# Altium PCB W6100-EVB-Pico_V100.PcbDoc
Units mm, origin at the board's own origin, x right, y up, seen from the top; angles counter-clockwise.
Board outline 75 x 21 mm, 2 copper layers (Top Layer, Bottom Layer); 85 components, 83 nets, 391 pads, 152 vias.
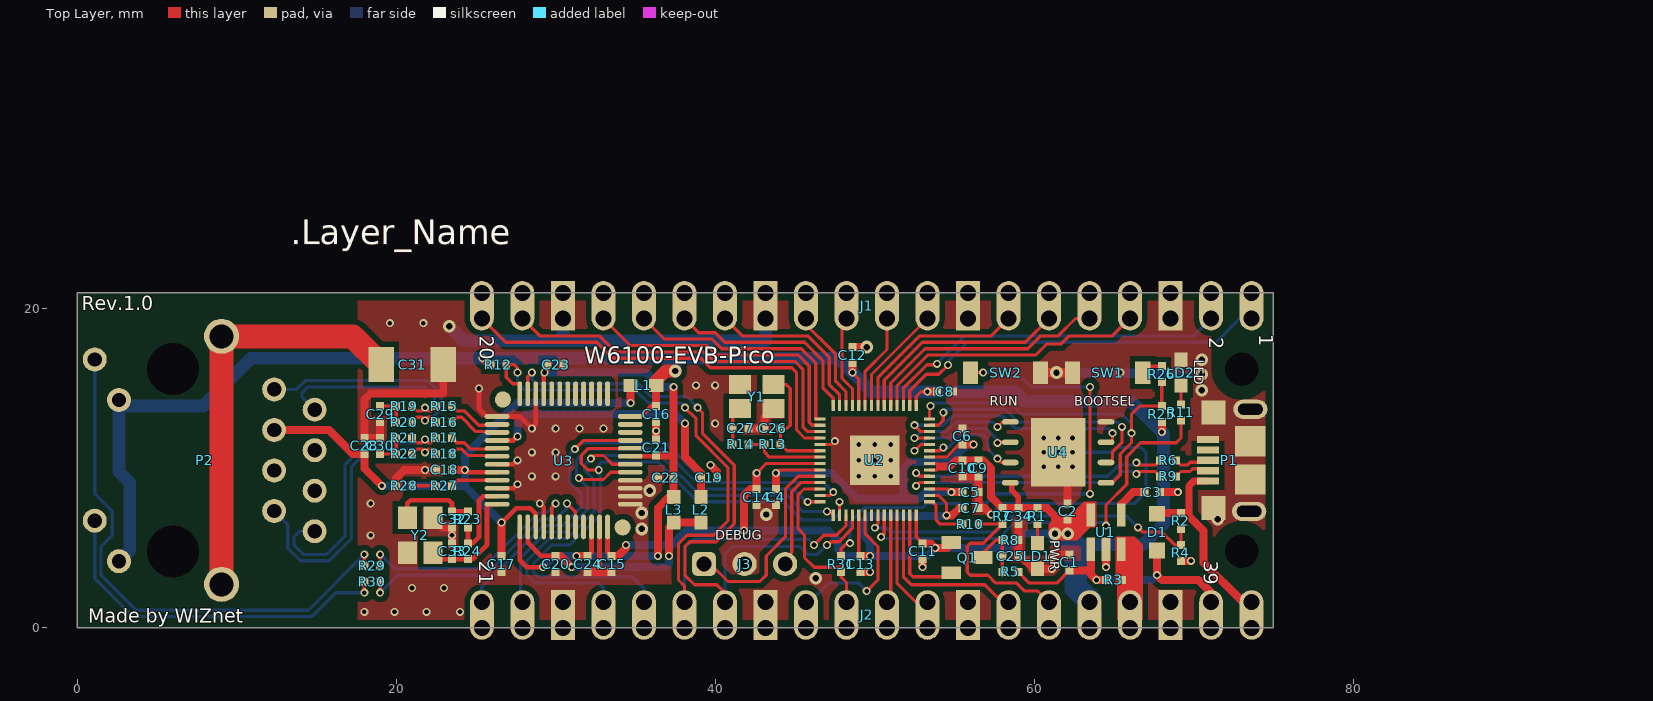
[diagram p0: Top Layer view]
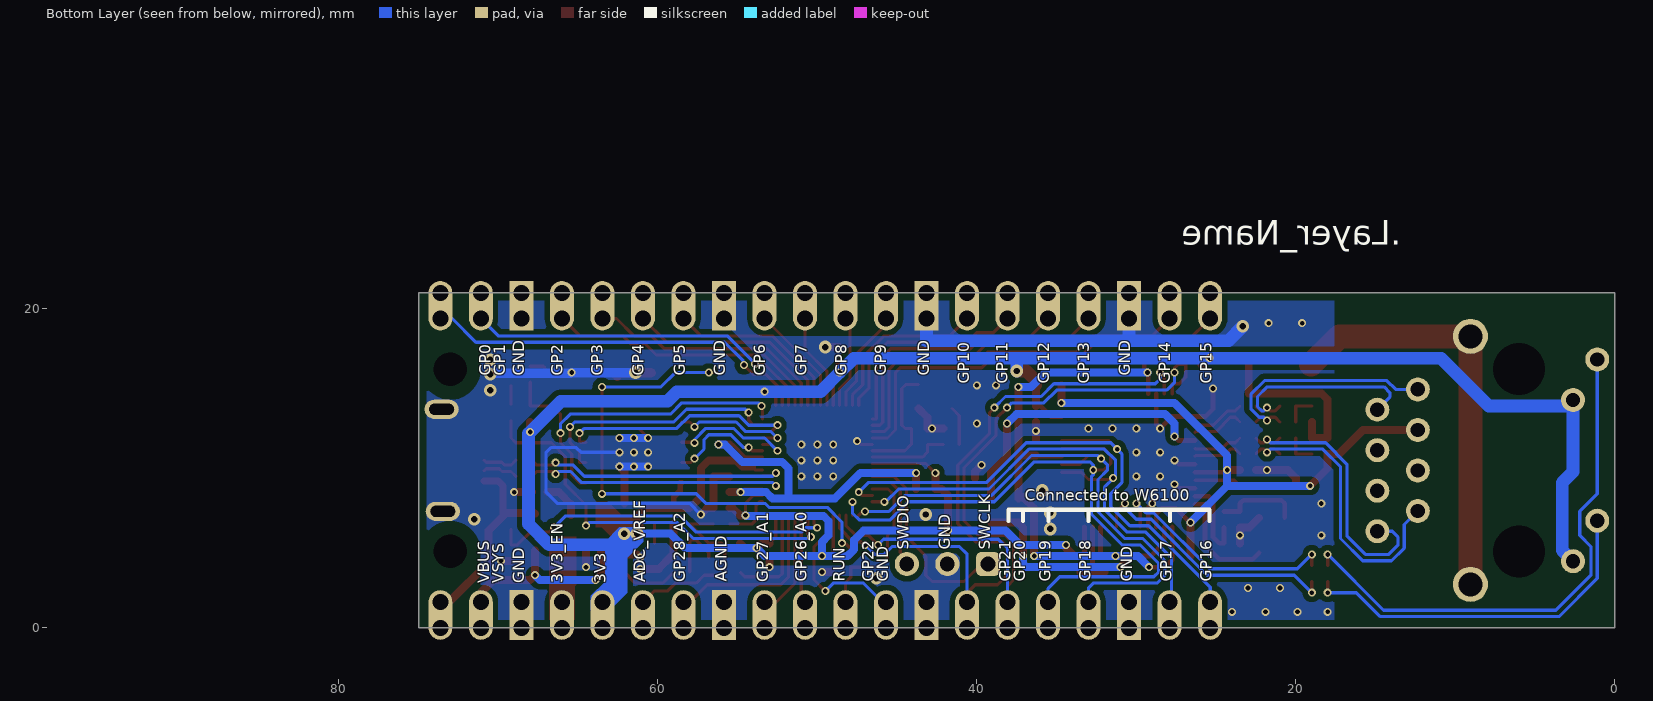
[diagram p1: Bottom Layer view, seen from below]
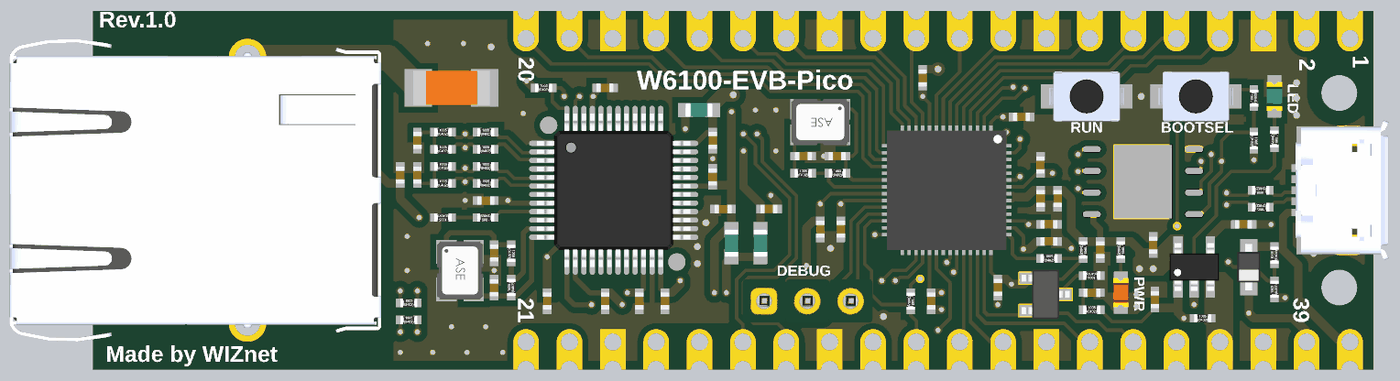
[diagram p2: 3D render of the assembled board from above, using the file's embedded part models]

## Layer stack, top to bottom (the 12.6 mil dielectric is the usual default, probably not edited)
Top Solder: solder mask 0.0102, Solder Resist, Dk 3.5
Top Layer: signal copper 0.0356
Dielectric1: prepreg 0.32, FR-4, Dk 4.8
Bottom Layer: signal copper 0.0356
Bottom Solder: solder mask 0.0102, Solder Resist, Dk 3.5

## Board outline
0,0 75,0 75,21 0,21

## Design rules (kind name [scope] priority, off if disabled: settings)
BoardOutlineClearance [All] p1: gap=0.5 ignorepadtopadclearanceinfootprint=FALSE
Clearance [All] p1: gap=0.2 ignorepadtopadclearanceinfootprint=FALSE except(0: Arc-Hole Track-Hole SMDPad-Hole THPad-Hole Via-Hole Fill-Hole Poly-Hole Region-Hole Text-Hole; 0.35: Arc-Poly Track-Poly SMDPad-Poly THPad-Poly Via-Poly Fill-Poly Poly-Poly Poly-Region Poly-Text)
DiffPairsRouting [All] p1: maxlimit=0.2 minlimit=0.2 mostfreqgap=0.2 toplayer_minwidth=0.2 toplayer_maxwidth=0.2 toplayer_prefwidth=0.2 bottomlayer_minwidth=0.2 bottomlayer_maxwidth=0.2 bottomlayer_prefwidth=0.2 maxuncoupledlength=15.24
HoleSize [All] p1: absolutevalues=TRUE maxlimit=4.064 minlimit=0.025 maxpercent=80.000 minpercent=20.000
PlaneClearance [All] p1: clearance=0.3
PlaneConnect [All] p1: planeconnectstyle=Direct reliefexpansion=0.508 reliefentries=4 reliefconductorwidth=0.254 reliefairgap=0.254
PolygonConnect [All] p1: connectstyle=Direct reliefconductorwidth=0.6 reliefentries=4 polygonreliefangle="45 Angle" airgapwidth=0.35
RoutingVias [All] p1: holewidth=0.3 width=0.5 viastyle="Through Hole" minholewidth=0.3 minwidth=0.5 maxholewidth=0.5 maxwidth=0.8
SolderMaskExpansion [All] p1: expansion=0 istentingtop=FALSE
Width [All] p1: maxlimit=2 minlimit=0.1 preferedwidth=0.2 minimp=50.000000 maximp=50.000000 favimp=50.000000
26 further rules are at their usual default settings.

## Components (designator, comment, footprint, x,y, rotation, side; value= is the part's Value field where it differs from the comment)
C1 "1uF" CAP-0402 62.2,4.1 r270 top
C2 "1uF" CAP-0402 62.1,7.3 r270 top
C3 "0.1uF" CAP-0402 67.4,8.5 r180 top
C4 "1uF" CAP-0402 43.8,8.2 r90 top
C5 "0.1uF" CAP-0402 56,8.5 r180 top
C6 "0.1uF" CAP-0402 55.5,12 r270 top
C7 "1uF" CAP-0402 56,7.5 r180 top
C8 "0.1uF" CAP-0402 54.4,14.8 r180 top
C9 "0.1uF" CAP-0402 56.5,10 r90 top
C10 "0.1uF" CAP-0402 55.5,10 r90 top
C11 "0.1uF" CAP-0402 53,4.8 r90 top
C12 "0.1uF" CAP-0402 48.6,17.1 r270 top
C13 "0.1uF" CAP-0402 49.1,4 r90 top
C14 "0.1uF" CAP-0402 42.6,8.2 r90 top
C15 "0.1uF" CAP-0402 33.5,4 r90 top
C16 "0.1uF" CAP-0402 36.3,13.4 r90 top
C17 "0.1uF" CAP-0402 26.6,4 r90 top
C18 "0.1uF" CAP-0402 23,9.9 r0 top
C19 "0.1uF" CAP-0402 39.6,9.4 r180 top
C20 "1uF" CAP-0402 30,4 r90 top
C21 "0.1uF" CAP-0402 36.3,11.3 r270 top
C22 "0.1uF" CAP-0402 36.9,9.4 r0 top
C23 "0.1uF" CAP-0402 30,16.5 r180 top
C24 "0.1uF" CAP-0402 32,4 r90 top
C25 "0.1uF" CAP-0402 58.5,4.5 r0 top
C26 "15pF" CAP-0402 43.6,12.5 r180 top
C27 "15pF" CAP-0402 41.6,12.5 r0 top
C28 "0.1uF" CAP-0402 18,11.4 r270 top
C29 "0.1uF" CAP-0402 19,13.4 r90 top
C30 "0.1uF" CAP-0402 19,11.4 r270 top
C31 "1nF/2kV" CAP-1808 21,16.5 r180 top
C32 "18pF" CAP-0402 23.5,6.8 r90 top
C33 "18pF" CAP-0402 23.5,4.8 r270 top
C34 "0.1uF" CAP-0402 59,7 r90 top
D1 "BAT60A" SOD-323(1-C,2-A) 67.7,6 r90 top
J1 "2.54mm 1x20 Pin Header DIP" IDC-1X20 73.63,19.39 r180 top
J2 "2.54mm 1x20 Pin Header DIP" IDC-1X20 25.37,1.61 r0 top
J3 "2.54mm 1x3 Pin Header DIP" IDC-1X3 39.3,4 r0 top
L1 "HH-1M1608-121JT" IND-0603 35.5,15.2 r180 top
L2 "HH-1M1608-121JT" IND-0603 39.1,7.4 r270 top
L3 "HH-1M1608-121JT" IND-0603 37.4,7.4 r90 top
LD1 "Red" LED-0603-RED 60.2,4.5 r270 top
LD2 "Green" LED-0603-GREEN 69.2,16 r90 top
P1 "Micro USB" "Micro 5P B DBX 6.4" 75,10.5 r180 top
P2 "RB1-125BAG1A" RB1-125BAG1A 6,10.5 r270 top
Q1 "Q-2N7002" SOT23-3L 55.8,4.4 r270 top
R1 "470R" RES-0402 60.2,7 r270 top
R2 "5.6K" RES-0402 69.2,6.7 r90 top
R3 "100K" RES-0402 65,3 r0 top
R4 "10K" RES-0402 69.2,4.7 r90 top
R5 "200K" RES-0402 58.5,3.5 r0 top
R6 "27R" RES-0402 68.4,10.5 r180 top
R7 "200R" RES-0402 58,7 r270 top
R8 "100K" RES-0402 58.5,5.5 r180 top
R9 "27R" RES-0402 68.4,9.5 r180 top
R10 "1R" RES-0402 56,6.5 r0 top
R11 "470R" RES-0402 69.2,13.5 r270 top
R12 "4.7K" RES-0402 26.4,16.5 r0 top
R13 "NC" RES-0402 43.6,11.5 r0 top
R14 "1K" RES-0402 41.6,11.5 r0 top
R15 "3.3R" RES-0402 23,13.9 r0 top
R16 "3.3R" RES-0402 23,12.9 r0 top
R17 "3.3R" RES-0402 23,11.9 r0 top
R18 "3.3R" RES-0402 23,10.9 r0 top
R19 "49.9R" RES-0402 20.5,13.9 r0 top
R20 "49.9R" RES-0402 20.5,12.9 r0 top
R21 "49.9R" RES-0402 20.5,11.9 r0 top
R22 "49.9R" RES-0402 20.5,10.9 r0 top
R23 "0R" RES-0402 24.5,6.8 r270 top
R24 "1M" RES-0402 24.5,4.8 r90 top
R25 "NC" RES-0402 68,13.4 r270 top
R26 "1K" RES-0402 68,15.9 r90 top
R27 "12K/1%" RES-0402 23,8.9 r180 top
R28 "300R" RES-0402 20.5,8.9 r180 top
R29 "470R" RES-0402 18.5,3.9 r0 top
R30 "470R" RES-0402 18.5,2.9 r0 top
R31 "1K" RES-0402 47.9,4 r270 top
SW1 "PTS820" 1185A 64.6,16 r180 top
SW2 "PTS820" 1185A 58.2,16 r0 top
U1 "LM8805SF5-33V" SOT-23-5L 64.5,6 r90 top
U2 "RP2040" QFN56(0.4/7X7) 50,10.5 r270 top
U3 "W5100S" LQFP48(0.5/9.0) 30.5,10.5 r0 top
U4 "W25Q16JVZPIM" WSON8(6X5_1.27) 61.5,11 r180 top
Y1 "12MHz" OSC-TZ1067B 42.6,14.5 r180 top
Y2 "25MHz" OSC-82J0626 21.5,5.8 r270 top

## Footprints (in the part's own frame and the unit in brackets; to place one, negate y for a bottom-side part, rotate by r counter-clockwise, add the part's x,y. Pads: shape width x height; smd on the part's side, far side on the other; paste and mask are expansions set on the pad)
1185A [mm]
  rect 0.95x1.4 smd: 1(-2.2,0) 2(2.2,0)
  body extent -2.18,-1.45 2.18,1.45, height 1.7
CAP-0402 [mm]
  rect 0.5x0.5 smd: 1(-0.5,0) 2(0.5,0)
  body extent -0.48,-0.25 0.52,0.25, height 0.6
CAP-1808 [mm] "Ceramic CAP 1808(4520)"
  rect 1.6x2.2 smd: 1(-1.95,0) 2(1.95,0)
  body extent -2.25,-1.02 2.25,1.01, height 2
IDC-1X3 [mil]
  rrect50% 60x60 hole 36: 1(0,0)
  round 60 hole 36: 2(100,0) 3(200,0)
  body extent -49,-49 251,51, height 336
IDC-1X20 [mm]
  oval 1.5x2.5 hole 1 copper offset 0,-0.5: 1(0,0) 2(2.54,0) 4(7.62,0) 5(10.16,0) 6(12.7,0) 7(15.24,0) 9(20.32,0) 10(22.86,0) 11(25.4,0) 12(27.94,0) 14(33.02,0) 15(35.56,0) 16(38.1,0) 17(40.64,0) 19(45.72,0) 20(48.26,0)
  oval 1.5x2.5 hole 1 copper offset 0,0.5: 1(0,-1.61) 2(2.54,-1.61) 4(7.62,-1.61) 5(10.16,-1.61) 6(12.7,-1.61) 7(15.24,-1.61) 9(20.32,-1.61) 10(22.86,-1.61) 11(25.4,-1.61) 12(27.94,-1.61) 14(33.02,-1.61) 15(35.56,-1.61) 16(38.1,-1.61) 17(40.64,-1.61) 19(45.72,-1.61) 20(48.26,-1.61)
  rect 1.5x2.5 hole 1 copper offset 0,0.5: 3(5.08,-1.61) 8(17.78,-1.61) 13(30.48,-1.61) 18(43.18,-1.61)
  rect 1.5x2.5 hole 1 copper offset 0,-0.5: 3(5.08,0) 8(17.78,0) 13(30.48,0) 18(43.18,0)
IND-0603 [mm] "Inductor 0603(1608)"
  rect 0.89x0.82 smd: 1(-0.8,0) 2(0.8,0)
  body extent -0.8,-0.4 0.8,0.4, height 0.95
LED-0603-GREEN [mm] "LED-0603-GREEN"
  rect 0.89x0.82 smd: 1(-0.8,0) 2(0.8,0)
  body extent -0.85,-0.45 0.85,0.45, height 0.9
LED-0603-RED [mm] "LED-0603-RED"
  rect 0.89x0.82 smd: 1(-0.8,0) 2(0.8,0)
  body extent -0.85,-0.45 0.85,0.45, height 0.9
LQFP48(0.5/9.0) [mm]
  round 1.016 smd: 0(-3.81,3.81) 0(3.7,-4.2)
  oval 1.55x0.3 smd: 1(-4.175,2.75) 2(-4.175,2.25) 3(-4.175,1.75) 4(-4.175,1.25) 5(-4.175,0.75) 6(-4.175,0.25) 7(-4.175,-0.25) 8(-4.175,-0.75) 9(-4.175,-1.25) 10(-4.175,-1.75) 11(-4.175,-2.25) 12(-4.175,-2.75) 25(4.175,-2.75) 26(4.175,-2.25) 27(4.175,-1.75) 28(4.175,-1.25) 29(4.175,-0.75) 30(4.175,-0.25) 31(4.175,0.25) 32(4.175,0.75) 33(4.175,1.25) 34(4.175,1.75) 35(4.175,2.25) 36(4.175,2.75)
  oval 0.3x1.55 smd: 13(-2.75,-4.175) 14(-2.25,-4.175) 15(-1.75,-4.175) 16(-1.25,-4.175) 17(-0.75,-4.175) 18(-0.25,-4.175) 19(0.25,-4.175) 20(0.75,-4.175) 21(1.25,-4.175) 22(1.75,-4.175) 23(2.25,-4.175) 24(2.75,-4.175) 37(2.75,4.175) 38(2.25,4.175) 39(1.75,4.175) 40(1.25,4.175) 41(0.75,4.175) 42(0.25,4.175) 43(-0.25,4.175) 44(-0.75,4.175) 45(-1.25,4.175) 46(-1.75,4.175) 47(-2.25,4.175) 48(-2.75,4.175)
  body extent -4.5,-4.5 4.5,4.5, height 1.5
"Micro 5P B DBX 6.4" [mm]
  rect 1.38x0.45 smd: 1(4.11,1.3) 2(4.11,0.65) 3(4.11,0) 4(4.11,-0.65) 5(4.11,-1.3)
  oval 2.15x1.2 hole 0.7 slot 1.55 at 0 deg: 6(1.524,3.2) 7(1.45,-3.2)
  rect 1.9x1.9 smd: 8(1.45,1.2) 9(1.45,-1.2)
  rect 1.5x1.5 smd: 10(3.75,-3) 11(3.75,3)
  body extent -0.88,-4.1 4.55,4.1, height 2.68
OSC-82J0626 [mm]
  rect 1.4x1.2 smd: 1(-1.1,-0.8) 2(1.1,-0.8) 3(1.1,0.8) 4(-1.1,0.8)
  body extent -1.7,-1.35 1.7,1.35, height 1.06
OSC-TZ1067B [mm]
  rect 1.4x1.2 smd: 1(-1.05,-0.75) 2(1.05,-0.75) 3(1.05,0.75) 4(-1.05,0.75)
  body extent -1.7,-1.35 1.7,1.35, height 1.06
QFN56(0.4/7X7) [mm]
  rect 0.7x0.2 smd: 1(-3.44,2.6) 2(-3.44,2.2) 3(-3.44,1.8) 4(-3.44,1.4) 5(-3.44,1) 6(-3.44,0.6) 7(-3.44,0.2) 8(-3.44,-0.2) 9(-3.44,-0.6) 10(-3.44,-1) 11(-3.44,-1.4) 12(-3.44,-1.8) 13(-3.44,-2.2) 14(-3.44,-2.6) 29(3.44,-2.6) 30(3.44,-2.2) 31(3.44,-1.8) 32(3.44,-1.4) 33(3.44,-1) 34(3.44,-0.6) 35(3.44,-0.2) 36(3.44,0.2) 37(3.44,0.6) 38(3.44,1) 39(3.44,1.4) 40(3.44,1.8) 41(3.44,2.2) 42(3.44,2.6)
  rect 0.2x0.7 smd: 15(-2.6,-3.44) 16(-2.2,-3.44) 17(-1.8,-3.44) 18(-1.4,-3.44) 19(-1,-3.44) 20(-0.6,-3.44) 21(-0.2,-3.44) 22(0.2,-3.44) 23(0.6,-3.44) 24(1,-3.44) 25(1.4,-3.44) 26(1.8,-3.44) 27(2.2,-3.44) 28(2.6,-3.44) 43(2.6,3.44) 44(2.2,3.44) 45(1.8,3.44) 46(1.4,3.44) 47(1,3.44) 48(0.6,3.44) 49(0.2,3.44) 50(-0.2,3.44) 51(-0.6,3.44) 52(-1,3.44) 53(-1.4,3.44) 54(-1.8,3.44) 55(-2.2,3.44) 56(-2.6,3.44)
  rect 3.1x3.1 smd: 57(0,0)
  body extent -3.5,-3.5 3.5,3.5, height 0.8
RB1-125BAG1A [mm]
  round 1.5 hole 0.9: L1(6.325,-3.38) L2(3.785,-4.9) L3(-3.785,-3.38) L4(-6.325,-4.9) R1(-4.445,6.35) R2(-3.175,8.89) R3(-1.905,6.35) R4(-0.635,8.89) R5(0.635,6.35) R6(1.905,8.89) R7(3.175,6.35) R8(4.445,8.89)
  round 2.2 hole 1.5: S1(-7.775,3.05) S2(7.775,3.05)
  round 3 hole 3.25 unplated paste+0 mask+0.102: ""(-5.715,0) ""(5.715,0)
  body extent -8.87,-10.89 8.88,10.89, height 14.02
RES-0402 [mm]
  rect 0.5x0.5 smd: 1(-0.5,0) 2(0.5,0)
  body extent -0.5,-0.25 0.5,0.25, height 0.35
SOD-323(1-C,2-A) [mm]
  rect 1x1 smd: 1(-1.15,0) 2(1.15,0)
  body extent -1.35,-0.67 1.35,0.68, height 0.79
SOT23-3L [mm]
  rect 0.8x1.2 smd paste-0.07: 1(-0.95,-1) 2(0.95,-1) 3(0,1)
  body extent -1.45,-1.4 1.45,1.4, height 1.28
SOT-23-5L [mm]
  rect 1.45x0.55 smd: 1(-1.075,0.95) 2(-1.075,0) 3(-1.075,-0.95) 4(1.075,-0.95) 5(1.075,0.95)
  body extent -1.4,-1.45 1.4,1.45, height 1.45
WSON8(6X5_1.27) [mm]
  oval 1.05x0.35 smd mask+0.05: 1(-3,1.905) 2(-3,0.635) 3(-3,-0.635) 4(-3,-1.905) 5(3,-1.905) 6(3,-0.635) 7(3,0.635) 8(3,1.905)
  rect 3.4x4.3 smd mask+0.05: 9(0,0)
  body extent -3,-2.5 3,2.5, height 0.8

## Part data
C1 C2 C3 C4 C5 C6 C7 C8 C9 C10 C11 C12 C13 C14 C15 C16 C17 C18 C19 C20 C21 C22 C23 C24 C25 C26 C27 C28 C29 C30 C32 C33 C34: library part CAP-0402, "Ceramic CAP 0402(1005)"
C31: library part CAP-1808, "Ceramic CAP 1808(4520)"
D1: library part DIODE-BAT60A, "Silicon Schottky Diode"
L1 L2 L3: library part IND-0603, "Inductor 0603(1608)"
LD1 LD2: library part LED-0603, "LED-0603"
P1: library part "Micro USB 5P DBX6.4", "Micro USB B Connector SMD"
Q1: "N-Channel 60-V (D-S) MOSFET"
R1 R2 R3 R4 R5 R6 R7 R8 R9 R10 R11 R12 R13 R14 R15 R16 R17 R18 R19 R20 R21 R22 R23 R24 R25 R26 R27 R28 R29 R30 R31: library part RES-0402, "RES-0402"
SW1 SW2: library part ITS-1107(SMD), "TACT Switch (SMD)"
U1: "600mA CMOS LDO Regulator"
U2: "Raspverry Pi, Dual ARM Cortex-M0+ @ 133MHz"
U3: "WIZnet Hardwired TCP/IP Chip"
U4: "3V 16M-BIT / SERIAL FLASH MEMORY WITH / DUAL/QUAD SPI, QPI & DTR"
Y1: library part OSC-TZ1067B-12MHz, "X-tal 12MHz,3.2x2.5 SMD, CL=20pF"
Y2: library part OSC-82J0626-25MHz, "X-tal 25MHz,3.2x2.5 SMD, CL=18pF"

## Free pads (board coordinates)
  round 0 hole 2.1 unplated: 0(73,4.8) 0(73,16.2)
  round 0 on Mech16 paste+0 mask+0: 1(96.4,35.9)

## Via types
v1: diameter 0.5, hole 0.3, Top Layer to Bottom Layer, tented both sides, 133 vias
v2: diameter 0.8, hole 0.4, Top Layer to Bottom Layer, tented both sides, 15 vias
v3: diameter 0.5, hole 0.3, Top Layer to Bottom Layer, 4 vias

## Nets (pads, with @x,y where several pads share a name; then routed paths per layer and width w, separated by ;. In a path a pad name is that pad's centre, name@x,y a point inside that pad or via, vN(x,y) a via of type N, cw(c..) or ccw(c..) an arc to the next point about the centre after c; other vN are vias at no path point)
1V1: C4.2 C5.2 C6.2 U2.23 U2.45 U2.50 | length 27.8
  Top Layer w0.2: v1(43.8,9.7) 44,9.9 U2.23 ; U2.45 54.6,8.7 v1(54.8,8.5) ; U2.50 54.5,10.7 55.3,11.5 C6.2
  Top Layer w0.5: C4.2 v1(43.8,9.7) ; v1(54.8,8.5) C5.2 ; C6.2 v1(56.2,11.5)
  Bottom Layer w0.5: v1(43.8,9.7) 47.3,9.7 48.9,8.1 51.8,8.1 ; v1(54.8,8.5) 53.2,8.5 52.8,8.1 51.8,8.1 ; v1(56.2,11.5) 55.8,11.5 54.7,10.4 52.2,10.4 51.8,10 51.8,8.1
1V2A: C19.2 L2.1 U3.4 | length 18.2
  Top Layer w0.3: U3.4 27.35,11.75 v1(27.6,12)
  Top Layer w0.5: v1(38.1,12.8) 38.1,10.7 39.1,9.7 C19.2 L2.1
  Bottom Layer w0.5: v1(27.6,12) 27.6,12.8 28.2,13.4 37.5,13.4 v1(38.1,12.8)
1V2D: C21.2 C22.2 C23.2 C24.2 L3.2 U3.13 U3.22 U3.31 U3.45 | length 38.3
  Top Layer w0.3: U3.13 27.75,4.25 28.2,3.8 v1(29.2,3.8) ; U3.45 29.25,15.9 29.25,16 v1(29.3,16) 29.5,16.2 C23.2 ; C24.2 32.25,4.75 U3.22 ; U3.31 36.25,10.75 C21.2
  Top Layer w0.5: v1(31.3,4.5) C24.2 ; C21.2 37.4,10.8 ; v1(36.4,4.5) 36.4,7.5 37.1,8.2 L3.2 ; L3.2@37.4,8.1 C22.2 37.4,10.8 ; v1(37.4,15.1) 37.4,10.8
  Bottom Layer w0.5: v1(29.2,3.8) 29.9,4.5 v1(31.3,4.5) ; v1(29.3,16) 35.7,16 36.6,15.1 v1(37.4,15.1) ; v1(31.3,4.5) v1(36.4,4.5)
1V2O: C20.2 L2.2 L3.1 U3.14 | length 15
  Top Layer w0.3: U3.14 28.25,5.35 29.1,4.5 C20.2
  Top Layer w0.5: C20.2 30.3,4.5 v1(31,3.8) ; v1(37.1,4.5) 37.1,6.3 L3.1 L2.2
  Bottom Layer w0.5: v1(31,3.8) 36.9,3.8 37.1,4 v1(37.1,4.5)
3V3: C2.2 C7.2 C8.2 C9.2 C10.2 C11.2 C12.2 C13.2 C14.2 C15.2 C16.2 C34.2 J2.16 L1.1 P2.L1 P2.L3 Q1.1 R1.1 R7.1 R12.1 R25.2 U1.5 U2.1 U2.10 U2.22 U2.33 U2.42 U2.44 U2.48 U2.49 U3.24 U3.36 U4.8 | length 176.9
  Top Layer w0.2: v1(42.6,9.7) 43.2,10.3 U2.22 ; v1(48.6,16) 49,15.6 U2.10 ; U2.33 49,4.6 C13.2 ; U2.42 52.6,5.7 C11.2 ; U2.1 52.6,14.5 52.9,14.8 v1(53.3,14.8) ; U2.44 54,8.3 54.5,7.8 v1(54.5,7.05) ; U2.48 53.9,9.9 54.1,10.1 53.9,10.3 U2.49 ; Q1.1 Q1.1@54.85,5.3
  Top Layer w0.3: U3.24 33.25,4.75 C15.2 ; U3.36 35.35,13.25 36,13.9 C16.2
  Top Layer w0.35: U4.8 58.6,9.095 58.6,8.6 59,8.2 C34.2
  Top Layer w0.5: v1(25.4,16.9) 25.8,16.5 R12.1 ; C15.2 33.9,4.5 34.4,5 v1(34.4,5.2) ; C16.2 L1.1 ; v1(41.8,6.1) 41.8,8.3 42.2,8.7 C14.2 v1(42.6,9.7) ; v1(48.6,16) C12.2 ; C13.2 v1(49.7,4.5) ; C11.2 53.5,5.3 v1(53.8,5) 54.55,5 Q1.1@54.85,5.3 ; v1(53.3,14.8) C8.2 ; 54.1,10.1 54.7,10.1 55.1,10.5 C10.2 C9.2 56.8,10.5 57.3,10 57.3,8.2 R7.1 C34.2 R1.1 60.8,7.5 61.3,7 v2(61.3,5.9) ; v1(54.5,7.05) 54.85,7.05 55.3,7.5 C7.2 ; v1(68,12.275) R25.2
  Top Layer w0.8: L1.1 36.3,15.5 36.9,16.1 v2(37.5,16.1)
  Bottom Layer w0.5: v1(34.4,5.2) 37.3,5.2 38.2,6.1 47.09,6.1 47.7,5.49 47.7,4.9 48.1,4.5 v1(49.7,4.5) ; v1(54.5,7.05) 54.45,7 49.6,7 49.307,6.707 49.307,5.778 49.7,5.385 v1(49.7,4.5) ; v2(61.3,5.9) 59.2,5.9 58.3,5 v1(53.8,5) 53.3,4.5 v1(49.7,4.5)
  Bottom Layer w0.8: P2.L1 3.3,4.855 3.3,9.1 2.62,9.78 P2.L3 3.005,13.9 7.9,13.9 10.9,16.9 v1(25.4,16.9) 37.5,16.9 ; v2(37.5,16.1) 37.5,16.9 ; v2(62.1,5.9) 62.8,5.2 66.8,5.2 68.1,6.5 68.1,12.175 v1(68,12.275) 66.075,14.2 59.39,14.2 59.095,14.495 58.79,14.8 v1(53.3,14.8) 49.8,14.8 v1(48.6,16) 47.7,16.9 37.5,16.9
3V3_EN: J2.17 R3.2 U1.3
3V3A: C17.2 C18.2 C28.2 L1.2 P2.R3 U3.8 U3.15 | length 40.4
  Top Layer w0.3: v1(24.3,9.9) 24.45,9.75 U3.8 ; v1(26.6,6.6) 26.613,6.6 27.513,7.5 28.407,7.5 28.75,7.157 U3.15
  Top Layer w0.5: P2.R3 15.795,12.405 17.3,10.9 C28.2 18,10 v1(19.1,8.9) ; C18.2 v1(24.3,9.9) ; C17.2 v1(26.6,6.6) ; v1(34.7,14.1) L1.2
  Bottom Layer w0.5: v1(19.1,8.9) 24.3,8.9 ; v1(26.6,6.6) 24.3,8.9 ; v1(34.7,14.1) 27.6,14.1 24.3,10.8 v1(24.3,9.9) 24.3,8.9
ACTn: R30.2 U3.20 | length 16.6
  Top Layer w0.2: v1(19,2.2) R30.2 ; v1(30.7,7.8) 31.25,7.25 U3.20
  Bottom Layer w0.2: v1(19,2.2) 20.1,3.3 25.566,3.3 29.066,6.8 30,6.8 30.7,7.5 v1(30.7,7.8)
ADC_VREF: J2.15 R7.2 R10.2 | length 11.8
  Top Layer w0.2: R10.2 R7.2 56.8,5.3 56,5.3 55.8,5.1 55.8,3.5 56,3.3 57.1,3.3 57.6,2.8 58.9,2.8 59.4,2.3 60.24,2.3 J2.15@60.93,1.61
CHGND: C31.2 P2.S1 P2.S2 | length 26.3
  Top Layer w1.5: P2.S2 P2.S1 17.275,18.275 C31.2
GND: C1.1 C2.1 C3.1 C4.1 C5.1 C6.1 C7.1 C8.1 C9.1 C10.1 C11.1 C12.1 C13.1 C14.1 C15.1 C16.1 C17.1 C18.1 C19.1 C20.1 C21.1 C22.1 C23.1 C24.1 C25.2 C26.2 C27.2 C28.1 C29.1 C30.1 C31.1 C32.1 C33.1 C34.1 J1.3 J1.8 J1.13 J1.18 J2.3 J2.8 J2.13 J2.18 J3.2 LD1.2 LD2.2 P1.5 P1.6 P1.7 P1.8 P1.9 P1.10 P1.11 R4.1 R8.1 R28.2 SW1.2 SW2.2 U1.2 U2.19 U2.57 U3.1 U3.7 U3.10 U3.16 U3.23 U3.25 U3.26 U3.27 U3.28 U3.46 U4.4 U4.9 Y1.2 Y1.4 Y2.2 Y2.4 | length 111.7
  Top Layer w0.2: U2.19 47.3,11.5 v1(47.5,11.7) ; v1(60.6,11.9) U4.9@61.1,12.4
  Top Layer w0.3: v1(25.2,15) 25.2,13.7 25.65,13.25 U3.1 27.75,13.25 v1(28.5,12.5) 28.75,12.75 U3.46 ; U3.10 27.35,8.75 v1(27.6,9) ; U3.7 27.35,10.25 v1(27.6,10.5) ; v1(29,7.8) 29.25,7.55 U3.16 ; 32.75,3.5 U3.23
  Top Layer w0.5: C29.1 C30.1 C28.1 18,14.3 18.4,14.7 22.95,14.7 C31.1 ; R28.2 20,9.4 20.5,9.9 v1(21.8,9.9) C18.1 ; Y2.4 22.9,6.3 C32.1 v1(23.5,5.8) C33.1 ; C24.1 32.75,3.5 C15.1 ; C21.1 v1(36.3,12.35) C16.1 ; v1(39.7,10.2) 40.1,9.8 C19.1 ; C27.2 C26.2 43.1,13.2 Y1.4 ; C12.1 v2(49.5,17.6) ; C13.1 v1(49.7,3.5) ; v1(53,3.8) C11.1 ; C10.1 C9.1 C5.1 C7.1 56.9,7.5 v1(57.3,7.1) ; C34.1 R8.1 C25.2 59.137,4.5 59.937,3.7 LD1.2 v1(61.1,3.7) ; v1(61.1,4.4) 61.3,4.6 C1.1 ; C2.1 62.1,9.8 v1(62.4,10.1) ; v1(64.5,3.8) U1.2 ; C3.1 v1(69,8.5) ; R4.1 v1(69.825,4.2)
  Top Layer w0.6: SW2.2 v2(61.4,16) 62.325,16 SW1.2@62.55,15.775
  Bottom Layer w0.2: v1(57.3,7.1) 58,7.8 66.3,7.8 67,8.5 67,11 66.7,11.3 65.1,11.3 64.8,11 v1(62.4,11)
  Bottom Layer w0.5: v1(60.6,10.1) v1(61.5,10.1) v1(62.4,10.1) ; v1(60.6,11.9) v1(61.5,11.9) v1(62.4,11.9)
  Bottom Layer w0.6: v2(61.4,16) v1(65.4,16) 65.45,15.95 70.45,15.95 v2(70.5,15.9)
  Bottom Layer w0.8: v2(23.322,18.9) 24.222,18 30.45,18 ; J1.18@30.45,19.39 30.45,18 ; J1.13@43.15,19.39 43.15,18 30.45,18
  other v1: 18,1 19.9,1 21.9,1 24,1 21,2.5 23,2.5 18.4,5.8 18.4,7.8 28.5,9.5 30,9.5 49,9.5 50,9.5 51,9.5 49,10.5 50,10.5 51,10.5 28.5,11 30,11 60.6,11 61.5,11 49,11.5 50,11.5 51,11.5 30,12.5 31.5,12.5 33,12.5 42.8,12.5 40,12.8 38.8,15.2 40,15.2 19.6,19.1 21.7,19.1
  other v2: 46.3,3.1 35.4,6.2 71.5,6.8 43.2,7.1 35.4,7.2 35.9,8.6 70.5,14.9 70.5,16.8
GPIO0: J1.1 U2.2 | length 24.3
  Top Layer w0.2: U2.2 52.2,14.852 53.243,15.895 54.023,15.895 v1(54.595,16.467)
  Bottom Layer w0.2: v1(54.595,16.467) 54.652,16.525 54.652,16.737 55.816,17.9 71.4,17.9 72.89,19.39 J1.1@73.63,19.39
GPIO1: J1.2 U2.3 | length 22.2
  Top Layer w0.2: U2.3 51.8,15.017 53.275,16.493 53.843,16.493 v1(53.9,16.55)
  Bottom Layer w0.2: v1(53.9,16.55) 55.65,18.3 70,18.3 J1.2@71.09,19.39
GPIO2: J1.4 U2.4 | length 19.2
  Top Layer w0.2: U2.4 51.4,15.183 53.317,17.1 60.1,17.1 60.8,17.8 61.7,17.8 62.2,18.3 64.9,18.3 66.01,19.41 J1.4@66.01,21
GPIO3: J1.5 U2.5 | length 15.6
  Top Layer w0.2: U2.5 51,15.349 53.151,17.5 59.606,17.5 60.406,18.3 61.5,18.3 62.59,19.39 J1.5@63.47,19.39
GPIO4: J1.6 U2.6 | length 13.5
  Top Layer w0.2: U2.6 50.6,15.514 52.986,17.9 59.44,17.9 J1.6@60.93,19.39
GPIO5: J1.7 U2.7 | length 11.5
  Top Layer w0.2: U2.7 50.2,15.68 52.82,18.3 57.3,18.3 J1.7@58.39,19.39
GPIO6: J1.9 U2.8 | length 7.5
  Top Layer w0.2: U2.8 49.8,15.456 49.8,15.88 52.62,18.7 53.31,19.39 J1.9@53.31,18.81
GPIO7: J1.10 U2.9 | length 6
  Top Layer w0.2: U2.9 49.4,16.08 50.77,17.45 J1.10@50.77,19.39
GPIO8: J1.11 U2.11 | length 5.8
  Top Layer w0.2: J1.11@47.95,19.17 47.95,15.65 48.6,15 U2.11 ; J1.11@48.23,19.39 J1.11@48.45,19.17
GPIO9: J1.12 U2.12 | length 6.8
  Top Layer w0.2: J1.12@45.31,19.39 47.55,17.15 47.55,15.45 48.2,14.8 U2.12 ; J1.12@45.69,19.39 J1.12@45.81,19.39
GPIO10: J1.14 U2.13 | length 12.4
  Top Layer w0.2: J1.14@40.61,21 40.61,19.39 41.7,18.3 45.8,18.3 47.15,16.95 47.15,15.25 47.8,14.6 U2.13
GPIO11: J1.15 U2.14 | length 14.5
  Top Layer w0.2: J1.15@38.07,21 38.07,19.39 38.96,18.5 40,18.5 40.6,17.9 45.6,17.9 46.75,16.75 46.75,15.05 47.4,14.4 U2.14
GPIO12: J1.16 U2.15 | length 15.7
  Top Layer w0.2: J1.16@35.53,19.39 36.82,18.1 39.8,18.1 40.4,17.5 45.4,17.5 46.3,16.6 46.3,13.1 U2.15
GPIO13: J1.17 U2.16 | length 18.4
  Top Layer w0.2: J1.17@32.99,19.39 34.68,17.7 39.5,17.7 40.1,17.1 45.2,17.1 45.9,16.4 45.9,12.886 46.086,12.7 U2.16
GPIO14: J1.19 U2.17 | length 23.7
  Top Layer w0.2: J1.19@27.91,19.39 29,18.3 32.734,18.3 33.734,17.3 39.3,17.3 39.9,16.7 45,16.7 45.5,16.2 45.5,12.6 45.8,12.3 U2.17
GPIO15: J1.20 U2.18 | length 26.4
  Top Layer w0.2: J1.20@25.37,19.39 26.86,17.9 32.569,17.9 33.569,16.9 39.1,16.9 39.7,16.3 44.8,16.3 45.1,16 45.1,12.4 45.6,11.9 U2.18
GPIO16: J2.1 U2.27 U3.33 | length 37.2
  Top Layer w0.2: v1(31.2,11.2) 31.75,11.75 U3.33 ; U2.27 47.2,8.3 v1(47.4,8.5)
  Bottom Layer w0.2: J2.1@25.37,0 25.37,1.61 25.37,2.539 29.231,6.4 30.4,6.4 31.6,7.6 31.6,8.4 30.9,9.1 30.9,10.9 v1(31.2,11.2) 31.6,11.6 36.9,11.6 39.4,9.1 46.8,9.1 v1(47.4,8.5)
GPIO17: J2.2 U2.28 U3.29 | length 33.7
  Top Layer w0.2: v1(31.45,9.4) 31.55,9.3 33,9.3 33.45,9.75 U3.29 ; v1(45.8,7.9) U2.28
  Bottom Layer w0.2: J2.2@27.91,0 27.91,1.61 27.8,1.72 27.8,3.1 27.8,4.403 29.397,6 30.566,6 32,7.434 32,8.8 v1@31.4,9.4 ; v1(31.45,9.4) 31.3,9.55 31.3,10.5 32,11.2 36.734,11.2 39.234,8.7 44.9,8.7 45.7,7.9 v1(45.8,7.9)
GPIO18: J2.4 U2.29 U3.30 | length 37.4
  Top Layer w0.2: v1(32.2,10.6) 32.4,10.8 33,10.8 33.55,10.25 U3.30 ; v1(47,7.3) 47.16,7.3 U2.29
  Bottom Layer w0.2: J2.4@32.99,0 32.99,1.61 32.99,2.51 32.7,2.8 28.7,2.8 28.2,3.3 28.2,4.2 29.6,5.6 30.731,5.6 32.4,7.269 32.4,9.3 31.8,9.9 31.8,10.2 v1(32.2,10.6) 32.4,10.8 36.569,10.8 39.069,8.3 44.5,8.3 45.5,7.3 v1(47,7.3)
GPIO19: J2.5 U2.30 U3.32 | length 40.8
  Top Layer w0.2: v1(32.7,9.9) 32,9.9 31.6,10.3 31.6,10.8 32.05,11.25 U3.32 ; U2.30 v1(47.8,7.9)
  Bottom Layer w0.2: J2.5@35.53,1.61 35.53,2.47 34.8,3.2 28.9,3.2 28.6,3.5 28.6,4.034 29.766,5.2 30.897,5.2 32.8,7.103 32.8,9.5 32.7,9.6 v1(32.7,9.9) 32.7,10.2 32.9,10.4 36.403,10.4 38.903,7.9 44.3,7.9 45.45,6.75 46.372,6.75 47.35,6.75 47.8,7.2 v1(47.8,7.9)
GPIO20: J2.6 R12.2 U2.31 U3.48 | length 49.3
  Top Layer w0.2: v1(27.6,16) 27.6,16.3 27.4,16.5 R12.2 26.9,15.7 27.3,15.3 27.75,15.3 U3.48 ; J2.6@38.07,0 38.07,1.61 38.07,2.63 37.7,3 37.7,5.266 38.234,5.8 39.9,5.8 40.8,6.7 40.8,10.034 38.8,12.034 38.8,13.1 v1(38.1,13.8) ; v1(46.2,5.2) 46.8,5.8 47.6,5.8 48.2,6.4 U2.31
  Bottom Layer w0.2: v1(27.6,16) 27.6,15.4 28.1,14.9 35,14.9 35.8,14.1 37.8,14.1 v1(38.1,13.8) ; J2.6@38.07,0 38.07,1.61 38.07,4.97 38.65,5.55 45.85,5.55 v1(46.2,5.2)
GPIO21: J2.7 U2.32 U3.47 | length 46.4
  Top Layer w0.2: U3.47 28.25,15.75 v1(28.5,16) ; v1(38.9,13.8) 39.2,13.5 39.2,12.2 41.2,10.2 41.2,6.534 40.066,5.4 38.4,5.4 38.1,5.1 38.1,3.3 38.7,2.7 40.1,2.7 40.61,2.19 40.61,1.61 J2.7@40.61,0 ; v1(47,5.2) 47.067,5.2 47.267,5.4 47.766,5.4 48.6,6.234 U2.32
  Bottom Layer w0.2: v1(28.5,16) 28.5,15.6 28.8,15.3 35.166,15.3 35.966,14.5 38.2,14.5 v1(38.9,13.8) ; J2.7@40.61,0 40.61,1.61 40.61,4.61 41.1,5.1 45.3,5.1 45.8,4.6 46.4,4.6 v1(47,5.2)
GPIO22: J2.9 U2.34 | length 12
  Top Layer w0.2: U2.34 49.4,5.9 50.2,5.1 50.2,3 v1(49.5,2.3)
  Bottom Layer w0.2: J2.9@45.69,0 J2.9@45.69,1.61 ; J2.9@45.69,2.09 J2.9@45.69,1.61 ; v1(49.5,2.3) 49,2.8 47.1,2.8 45.91,1.61 J2.9@45.69,1.61
GPIO24: R2.1 R4.2 U2.36 | length 22.3
  Top Layer w0.2: v1(50.007,6.273) 50.007,6.293 50,6.3 50.2,6.5 U2.36 ; v1(66.5,6.3) 66.8,6 68,6 68.8,5.2 R4.2 R2.1
  Bottom Layer w0.2: v1(50.007,6.273) 50.727,6.273 51,6 57.6,6 58.6,7 65.8,7 v1(66.5,6.3)
GPIO25: R11.2 U2.37 | length 25.9
  Top Layer w0.2: v1(50.409,5.7) 50.4,5.7 50.6,5.9 U2.37 ; v1(64.5,6.4) 64.5,7.7 65.8,9 65.8,10.734 66.666,11.6 68.9,11.6 69.2,11.9 R11.2
  Bottom Layer w0.2: v1(50.409,5.7) 50.509,5.6 57.766,5.6 58.766,6.6 64.3,6.6 v1(64.5,6.4)
GPIO26/ADC0: J2.11 U2.38 | length 7.2
  Top Layer w0.2: J2.11@50.77,0 50.77,1.61 51,1.84 U2.38
GPIO27/ADC1: J2.12 U2.39 | length 6.7
  Top Layer w0.2: U2.39 51.4,2.8 52.59,1.61 J2.12@53.31,1.61
GPIO28/ADC2: J2.14 U2.40 | length 11.1
  Top Layer w0.2: U2.40 51.8,3.2 52.3,2.7 56.9,2.7 57.99,1.61 J2.14@58.39,1.61
GPIO29/ADC3: Q1.2 U2.41 | length 6.4
  Top Layer w0.2: U2.41 52.2,3.4 52.4,3.2 54.55,3.2 Q1.2
LINKn: R29.2 U3.17 | length 15.3
  Top Layer w0.2: R29.2 v1(19,4.6) ; U3.17 29.75,7.55 v1(30,7.8)
  Bottom Layer w0.2: v1(19,4.6) 19.9,3.7 25.4,3.7 28.9,7.2 29.4,7.2 v1(30,7.8)
NetC3_2: C3.2 U1.4 | length 2.4
  Top Layer w0.5: U1.4 65.45,7.75 66.2,8.5 C3.2
NetC25_1: C25.1 Q1.3 R5.1 R8.2 | length 3.8
  Top Layer w0.2: Q1.3 56.8,4.7 57.6,5.5 R8.2 58,5.4 C25.1 R5.1
NetC27_1: C27.1 R14.1 Y1.3 | length 2.4
  Top Layer w0.2: R14.1 C27.1 41.1,13.3 Y1.3
NetC29_2: C29.2 R19.1 R20.1 | length 2
  Top Layer w0.2: C29.2 R19.1 R20.1
NetC30_2: C30.2 R21.1 R22.1 | length 2
  Top Layer w0.2: C30.2 R22.1 R21.1
NetC32_2: C32.2 R23.1 Y2.1 | length 5.4
  Top Layer w0.3: Y2.1 20.7,7.8 20.9,8 23.3,8 23.5,7.8 C32.2 R23.1
NetC33_2: C33.2 R24.1 U3.12 Y2.3 | length 7.1
  Top Layer w0.3: Y2.3 22.7,4.3 C33.2 R24.1 24.8,4.3 25.7,5.2 25.7,7.75 U3.12
NetLD1_1: LD1.1 R1.2 | length 1.2
  Top Layer w0.2: LD1.1 R1.2
NetLD2_1: LD2.1 R11.1 | length 1.2
  Top Layer w0.2: R11.1 LD2.1
NetP2_L2: P2.L2 R30.1 | length 22.8
  Top Layer w0.2: v1(18,2.2) R30.1
  Bottom Layer w0.2: P2.L2 1.1,3.1 3.5,0.7 14.7,0.7 16.2,2.2 v1(18,2.2)
NetP2_L4: P2.L4 R29.1 | length 33.8
  Top Layer w0.2: R29.1 v1(18,4.6)
  Bottom Layer w0.2: P2.L4 1.1,8.4 2.2,7.3 2.2,5.8 1.5,5.1 1.5,3.3 3.7,1.1 14.5,1.1 v1(18,4.6)
NetR6_2: R6.2 U2.47 | length 16.8
  Top Layer w0.2: v1(52.6,9.7) 52.8,9.5 U2.47 ; v1(66.4,10.35) 66.55,10.2 67.5,10.2 67.6,10.2 R6.2
  Bottom Layer w0.2: v1(52.6,9.7) 52.8,9.5 64.6,9.5 65.3,10.2 66.25,10.2 v1(66.4,10.35)
NetR9_2: R9.2 U2.46 | length 16.8
  Top Layer w0.2: v1(52.6,8.9) 52.8,9.1 U2.46 ; v1(66.4,9.65) 66.55,9.8 67.6,9.8 R9.2
  Bottom Layer w0.2: v1(52.6,8.9) 52.8,9.1 64.766,9.1 65.466,9.8 66.25,9.8 v1(66.4,9.65)
NetR10_1: R10.1 U2.43 | length 3.2
  Top Layer w0.2: U2.43 53.6,7.9 53.85,7.65 53.85,6.75 54.1,6.5 R10.1
NetR15_2: R15.2 U3.2 | length 3.3
  Top Layer w0.2: R15.2 23.8,13.6 24.266,13.6 25.166,12.7 26.275,12.7 U3.2
NetR16_2: R16.2 U3.3 | length 3.3
  Top Layer w0.2: R16.2 23.8,13.2 24.1,13.2 25,12.3 26.275,12.3 U3.3
NetR17_2: R17.2 U3.5 | length 3.1
  Top Layer w0.2: R17.2 23.8,11.6 24.266,11.6 24.666,11.2 26.275,11.2 U3.5
NetR18_2: R18.2 U3.6 | length 3.1
  Top Layer w0.2: R18.2 23.8,11.2 24.1,11.2 24.5,10.8 26.275,10.8 U3.6
NetR23_2: R23.2 R24.2 U3.11 | length 5.4
  Top Layer w0.3: R23.2 R24.2 24.8,5.3 25.2,5.7 25.2,8 25.45,8.25 U3.11
NetR26_2: R26.2 SW1.1 | length 1.2
  Top Layer w0.2: SW1.1@67.067,16.092 67.067,16.292 67.175,16.4 R26.2
NetR27_1: R27.1 U3.9 | length 3
  Top Layer w0.2: R27.1 23.85,9.25 U3.9
NetR27_2: R27.2 R28.1 | length 1.5
  Top Layer w0.2: R28.1 R27.2
NetR31_1: R31.1 SW2.1 | length 32.5
  Top Layer w0.2: R31.1 47.9,4.969 48.18,5.249 ; SW2.1 v3(56.8,16) ; v3(63.5,8.4) v3(63.5,15.1)
  Bottom Layer w0.2: v3(48.45,5.307) 48.45,6.628 49.372,7.55 53.028,7.55 53.278,7.8 56.988,7.8 57.588,8.4 v3(63.5,8.4) ; v3(56.8,16) 58.9,16 59.8,15.1 v3(63.5,15.1)
QSPI1_SCLK: U2.52 U4.6 | length 8.2
  Top Layer w0.2: v1(52.5,11.1) 52.9,11.5 U2.52 ; v1(57.7,11.6) 57.735,11.635 U4.6
  Bottom Layer w0.2: v1(52.5,11.1) 53.3,11.9 54.653,11.9 55.253,12.5 57,12.5 57.7,11.8 v1(57.7,11.6)
QSPI1_SD0: U2.53 U4.5 | length 7.6
  Top Layer w0.2: v1(52.5,11.9) U2.53 ; v1(57.7,12.6) 58.005,12.905 U4.5
  Bottom Layer w0.2: v1(52.5,11.9) 52.9,12.3 54.488,12.3 55.087,12.9 57.4,12.9 v1(57.7,12.6)
QSPI1_SD1: U2.55 U4.2 | length 16.1
  Top Layer w0.2: U2.55 54,12.7 54.3,13 v1(54.3,13.5) ; U4.2 64.9,10.365 64.9,11 65.5,11.6 v1(65.5,12.6)
  Bottom Layer w0.2: v1(54.3,13.5) 54.5,13.7 58.2,13.7 59,12.9 65.2,12.9 v1(65.5,12.6)
QSPI1_SD2: U2.54 U4.3 | length 15.1
  Top Layer w0.2: v1(52.5,12.7) 52.5,12.678 52.878,12.3 U2.54 ; U4.3 64.835,11.635 64.9,11.7 v1(64.9,12.2)
  Bottom Layer w0.2: v1(52.5,12.7) 54.3,12.7 54.9,13.3 58,13.3 58.8,12.5 64.6,12.5 v1(64.9,12.2)
QSPI1_SD3: U2.51 U4.7 | length 6.5
  Top Layer w0.2: U2.51 54.1,11.1 v1(54.3,11.3) ; v1(57.7,10.6) 57.935,10.365 U4.7
  Bottom Layer w0.2: v1(54.3,11.3) 54.619,11.3 55.419,12.1 56.8,12.1 57.1,11.8 57.1,11.2 v1(57.7,10.6)
QSPI1_SS_N: R25.1 R26.1 U2.56 U4.1 | length 23.5
  Top Layer w0.2: U2.56 53.44,13.84 v1(53.5,13.9) ; U4.1 64.895,9.095 65.398,9.598 65.398,10.898 66.1,11.6 v1(66.1,12.2) 66.1,13.4 66.6,13.9 R25.1 R26.1
  Bottom Layer w0.2: v1(53.5,13.9) 53.7,14.1 58.5,14.1 59.2,13.4 65.5,13.4 66.1,12.8 v1(66.1,12.2)
RUN: J2.10 R31.2 U2.26 | length 12.1
  Top Layer w0.2: U2.26 45.566,8.7 45.2,8.334 45.2,6.2 45.6,5.8 45.6,4.4 46.2,3.8 47.9,3.8 R31.2 47.9,3.17 48.23,2.84 48.23,1.61 J2.10@48.23,0
RX_N: P2.R8 R17.1 R21.2 | length 17.9
  Top Layer w0.2: R21.2 21.3,11.6 21.6,11.6 v1(21.8,11.8) 22,11.6 22.2,11.6 R17.1
  Bottom Layer w0.2: P2.R8 13.955,6.055 13.6,5.7 13.6,5.166 14.166,4.6 15.634,4.6 16.8,5.766 16.8,10.266 18.134,11.6 21.6,11.6 v1(21.8,11.8)
RX_P: P2.R7 R18.1 R22.2 | length 19.1
  Top Layer w0.2: R22.2 21.3,11.2 21.6,11.2 v1(21.8,11) 22,11.2 22.2,11.2 R18.1
  Bottom Layer w0.2: P2.R7 13.2,6.475 13.2,5 14,4.2 15.8,4.2 17.2,5.6 17.2,10.1 18.3,11.2 21.6,11.2 v1(21.8,11)
SWCLK: J3.1 U2.24 | length 12.9
  Top Layer w0.2: J3.1 39.7,4 40.8,2.9 42.8,2.9 43.2,3.3 43.2,4.5 44.4,5.7 44.4,8.7 45.2,9.5 U2.24
SWDIO: J3.3 U2.25 | length 6.4
  Top Layer w0.2: J3.3@44.38,4.3 44.8,4.72 44.8,8.534 45.366,9.1 U2.25
TX_N: P2.R2 R15.1 R19.2 | length 13.4
  Top Layer w0.2: R19.2 21.3,13.6 21.6,13.6 v1(21.8,13.8) 22,13.6 22.2,13.6 R15.1
  Bottom Layer w0.2: P2.R2 14.1,14.465 14.1,14.734 14.466,15.1 21.8,15.1 22.4,14.5 22.4,13.866 22.134,13.6 22,13.6 v1(21.8,13.8)
TX_P: P2.R1 R16.1 R20.2 | length 15.2
  Top Layer w0.2: R20.2 21.3,13.2 21.6,13.2 v1(21.8,13) 22,13.2 22.2,13.2 R16.1
  Bottom Layer w0.2: P2.R1 13.745,14.945 14.3,15.5 21.966,15.5 22.8,14.666 22.8,13.7 22.3,13.2 22,13.2 v1(21.8,13)
USB_DM: P1.2 R9.1 | length 2.2
  Top Layer w0.2: R9.1 69.2,9.8 69.766,9.8 69.941,9.975 70.765,9.975 P1.2
USB_DP: P1.3 R6.1 | length 2.2
  Top Layer w0.2: R6.1 69.2,10.2 69.6,10.2 69.775,10.375 70.765,10.375 P1.3
VBUS: D1.2 J2.20 P1.1 R2.2 | length 13
  Top Layer w0.45: R2.2 69.7,7.2 69.7,8.9 70,9.2 P1.1
  Top Layer w0.5: D1.2 67.75,7.2 R2.2 69.5,7.2 70.6,6.1 70.6,4.1 73.09,1.61 J2.20@73.63,1.61
VSYS: C1.2 D1.1 J2.19 R3.1 R5.2 U1.1 | length 17.8
  Top Layer w0.2: R5.2 59.7,2.8 61.4,2.8 C1.2
  Top Layer w0.5: C1.2 63.55,3.6 ; U1.1 63.55,3.6 ; R3.1 v1(63.9,3) 63.55,3.35 63.55,3.6 ; D1.1 v1(67.7,3.3) 68,3 70.3,3 71.09,2.21 J2.19@71.09,1.61
  Bottom Layer w0.5: v1(63.9,3) 67.4,3 v1(67.7,3.3)
XIN: C26.1 R13.2 U2.20 Y1.1 | length 7.8
  Top Layer w0.2: Y1.1 44.45,15.25 44.7,15 44.7,12.7 44.5,12.5 C26.1 R13.2 44.5,11.1 U2.20
XOUT: R13.1 R14.2 U2.21 | length 5.1
  Top Layer w0.2: R14.2 R13.1 43.1,11 43.4,10.7 U2.21
pads on no net: P1.4 P2. P2.R4 P2.R5 P2.R6 U2.35 U3.0 U3.18 U3.19 U3.21 U3.34 U3.35 U3.37 U3.38 U3.39 U3.40 U3.41 U3.42 U3.43 U3.44

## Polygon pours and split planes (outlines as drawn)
GND on Top Layer "NONET_L-01_P-001" (solid, remove dead copper, pour order 0): 17.6,0 17.6,21 75,21 75,0
GND on Bottom Layer "NONET_L-01_P-001" (solid, remove dead copper, pour order 1): 17.6,0 17.6,21 75,21 75,0

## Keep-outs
Keep-Out Layer:
  text ".Layer_Name" at 13.398,24 h1.52

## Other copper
Top Layer:
  region net 3V3: 61.3,5.5 62.7,5.5 63.5,6.3 63.9,6.3 63.9,7.9 63.1,7.9 62.3,7.1 61.5,7.1 60.9,6.5 60.9,5.9
  region net 3V3_EN: 65.2,0.5 65.2,2.6 65.1,2.7 65.1,5.7 66.3,5.7 66.8,5.2 66.8,0.5
  text ".Layer_Name" at 13.398,24 h1.52
Bottom Layer:
  region net 3V3: 64.2,1.1 64.2,2 63.3,2.9 63.3,5.4 62.4,6.3 61.3,6.3 60.9,5.9 60.9,5.4 61.9,4.4 61.9,2.2 63,1.1
  text ".Layer_Name" at 13.398,24 h1.52
Multi-Layer:
  pour cut-out: 71.1,16.2 ccw(c73,16.2) 73,14.3 ccw(c73,16.2) 74.9,16.2 ccw(c73,16.2) 73,18.1 ccw(c73,16.2)
  pour cut-out: 71.1,4.8 ccw(c73,4.8) 73,2.9 ccw(c73,4.8) 74.9,4.8 ccw(c73,4.8) 73,6.7 ccw(c73,4.8)
  pour cut-out: 58.39,2.713 61,2.713 61,2.5 58.39,2.5
  pour cut-out: 50.77,2.713 53.38,2.713 53.38,2.5 50.77,2.5
  pour cut-out: 71.1,4.894 71.1,2.7 70.9,2.5 71.5,2.5 71.5,4.9
  pour cut-out: 71.1,16.106 71.1,18.3 70.9,18.5 71.5,18.5 71.5,16.1
  pour cut-out: 66.01,18.287 58.39,18.287 58.39,18.5 66.01,18.5
  pour cut-out: 53.3,18.287 45.62,18.287 45.62,18.5 53.3,18.5
  pour cut-out: 40.61,18.287 33,18.287 33,18.5 40.61,18.5
  pour cut-out: 27.91,18.287 25.3,18.287 25.3,18.5 27.91,18.5
  pour cut-out: 25.37,2.713 27.98,2.713 27.98,2.5 25.37,2.5
  pour cut-out: 32.99,2.713 37.6,2.713 37.6,2.5 32.99,2.5

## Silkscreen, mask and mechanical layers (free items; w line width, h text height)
Top Overlay:
  text ".Layer_Name" at 13.398,24.032 h1.52
  text "Rev.1.0" at 0.3,19.6 h1.5
  text "1" at 73.8,18.4 h1.5 r270
  text "20" at 24.918,18.3 h1.5 r270
  text "2" at 70.662,18.219 h1.5 r270
  text "LED" at 69.8,16.8 h1 r270
  text "W6100-EVB-Pico" at 31.8,16.2 h1.8
  text "RUN" at 57.2,13.7 h1
  text "BOOTSEL" at 62.5,13.7 h1
  text "PWR" at 60.8,5.5 h1 r270
  text "DEBUG" at 40,5.3 h1
  text "21" at 24.9,4.2 h1.5 r270
  text "39" at 70.318,4.2 h1.5 r270
  text "Made by WIZnet" at 0.7,0 h1.5
Bottom Overlay:
  lines w0.254: 25.4,6.7 25.4,7.4 38,7.4 38,6.7 ; 27.9,6.7 27.9,7.4 ; 33,6.7 33,7.4 ; 35.5,6.7 35.5,7.4 ; 37.1,6.7 37.1,7.3
  text ".Layer_Name" at 13.398,24 h1.52
  text "GND" at 30.114,15.8 h1.2 r270
  text "GND" at 42.714,15.8 h1.2 r270
  text "GP9" at 45.414,15.8 h1.2 r270
  text "GP8" at 47.914,15.8 h1.2 r270
  text "GP7" at 50.414,15.8 h1.2 r270
  text "GP6" at 53.014,15.8 h1.2 r270
  text "GND" at 55.514,15.8 h1.2 r270
  text "GP5" at 58.014,15.8 h1.2 r270
  text "GP4" at 60.614,15.8 h1.2 r270
  text "GP3" at 63.214,15.8 h1.2 r270
  text "GP2" at 65.714,15.8 h1.2 r270
  text "GND" at 68.114,15.8 h1.2 r270
  text "GP1" at 69.314,15.8 h1.2 r270
  text "GP0" at 70.214,15.8 h1.2 r270
  text "GP15" at 25.014,15.3 h1.2 r270
  text "GP14" at 27.614,15.3 h1.2 r270
  text "GP13" at 32.714,15.3 h1.2 r270
  text "GP12" at 35.214,15.3 h1.2 r270
  text "GP11" at 37.814,15.3 h1.2 r270
  text "GP10" at 40.214,15.3 h1.2 r270
  text "Connected to W6100" at 37,7.714 h1.2
  text "SWCLK" at 38.914,4.9 h1.2 r270
  text "GND" at 41.414,4.9 h1.2 r270
  text "SWDIO" at 44.014,4.9 h1.2 r270
  text "GP16" at 25.014,2.9 h1.2 r270
  text "GP17" at 27.514,2.9 h1.2 r270
  text "GND" at 30.014,2.9 h1.2 r270
  text "GP18" at 32.614,2.9 h1.2 r270
  text "GP19" at 35.114,2.9 h1.2 r270
  text "GP20" at 36.714,2.9 h1.2 r270
  text "GP21" at 37.614,2.9 h1.2 r270
  text "GND" at 45.314,2.9 h1.2 r270
  text "GP22" at 46.214,2.9 h1.2 r270
  text "RUN" at 48.014,2.9 h1.2 r270
  text "GP26_A0" at 50.412,2.9 h1.2 r270
  text "AGND" at 55.414,2.9 h1.2 r270
  text "GP27_A1" at 52.836,2.861 h1.2 r270
  text "GP28_A2" at 58.036,2.861 h1.2 r270
  text "ADC_VREF" at 60.536,2.861 h1.2 r270
  text "3V3" at 63.014,2.8 h1.2 r270
  text "3V3_EN" at 65.712,2.8 h1.2 r270
  text "GND" at 68.114,2.8 h1.2 r270
  text "VSYS" at 69.414,2.8 h1.2 r270
  text "VBUS" at 70.314,2.8 h1.2 r270
Top Paste:
  text ".Layer_Name" at 13.398,24 h1.52
Bottom Paste:
  text ".Layer_Name" at 13.398,24 h1.52
Top Solder:
  text ".Layer_Name" at 13.398,24 h1.52
Bottom Solder:
  text ".Layer_Name" at 13.398,24 h1.52
Drill Guide:
  text ".Layer_Name" at 13.398,24 h1.52
Mechanical 2:
  the board outline again, w0.2
  text "BOARD NAME : W6100-EVB-Pico" at 4,35.176 h1.52
  text "VERSION : V100" at 4,32.382 h1.52
  text "SIZE : 75mmX21mmX1.0T" at 4,29.588 h1.52
  text "GERBER DATE : 2022. 10. 05" at 4,26.794 h1.52
  text "LAYER :" at 4,24 h1.52
Drill Drawing:
  text ".Layer_Name" at 13.398,24 h1.52

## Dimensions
-0.5,0 to -0.5,21 on Mechanical 2
0,-0.4 to 75,-0.5 on Mechanical 2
